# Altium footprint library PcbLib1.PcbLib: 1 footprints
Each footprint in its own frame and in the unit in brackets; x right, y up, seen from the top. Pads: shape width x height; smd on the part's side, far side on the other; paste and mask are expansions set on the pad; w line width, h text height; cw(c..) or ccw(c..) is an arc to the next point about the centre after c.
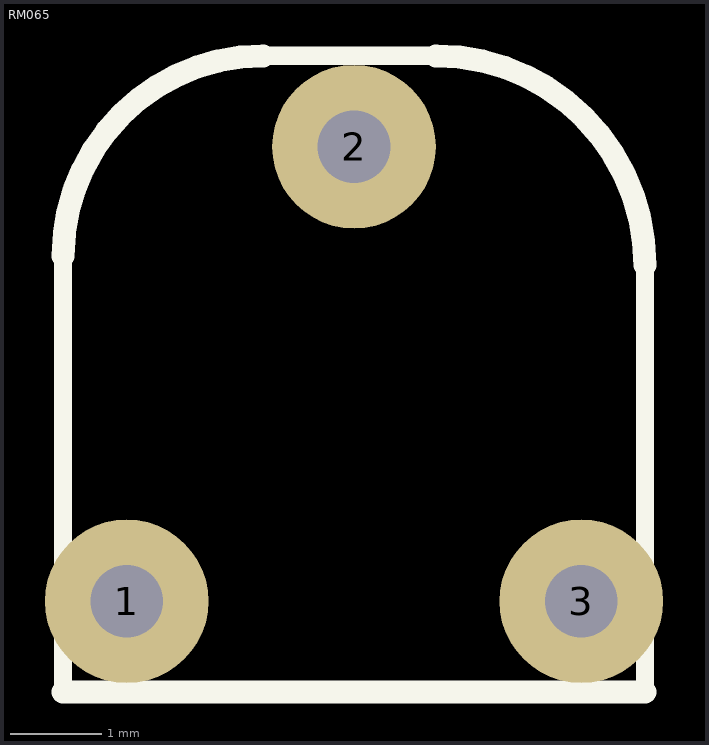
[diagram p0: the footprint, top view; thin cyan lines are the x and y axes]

## RM065 [mm]
pads (3):
  round 1.8 hole 0.8: 1(-582.5,-905) 2(-580,-900) 3(-577.5,-905)
Top Overlay:
  lines w0.2: -583.2,-906 -583.2,-901.2 ; -581,-899 -579.1,-899 ; -576.8,-906 -576.8,-901.3
  lines w0.254: -583.2,-906 -576.8,-906 ; -583.2,-901.2 cw(c-581,-901.2) -581,-899 ; -579.1,-899 cw(c-579.1,-901.3) -576.8,-901.3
